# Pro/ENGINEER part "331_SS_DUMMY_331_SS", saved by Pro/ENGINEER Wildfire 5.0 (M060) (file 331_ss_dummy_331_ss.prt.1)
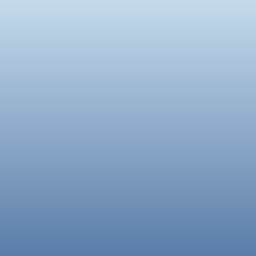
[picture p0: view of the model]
Units: PSOLunit; MM, KILOGRAM, SECS

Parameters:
  NN = "Series 331-SS_dummy"
  NT = "Stainless Steel Clamps - Latch Clamps"
  NB = "331-SS_dummy-331-SS"
  NBSYN = "$PN.-$S."
  LINA = "331-SS_dummy-331-SS"
  PN = "331-SS_dummy"
  S = "331-SS"
  SUPPLIER = "DESTACO"
  ARTICLENO = "331-SS_dummy-331-SS"
  BOMINFO = "331-SS_dummy-331-SS"
  CREATOR = "CADENAS GmbH"

Other parameters: SURF_AREA, MASS

Other named items: COORD, DEF-PLANE-AXIS, DEF-PLANE-AXIS-INV, DUMMY_CSYS, CONN, MASS, RIGHT, TOP, FRONT, DUMMY_XPLN, DUMMY_YPLN, DUMMY_ZPLN, DUMMY_ZAXS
